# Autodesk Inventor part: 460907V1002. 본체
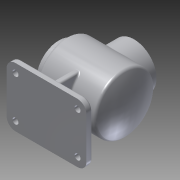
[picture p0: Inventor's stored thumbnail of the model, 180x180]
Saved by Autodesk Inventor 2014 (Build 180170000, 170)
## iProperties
Created: 2016-09
Part Number: 460907V1002. 본체
Material: 알루미늄 6061
Document SubType Name: Modeling
Designer: 702
Density: 2.71 g/cm^3
Appearance: 알루미늄 - 평지
Mass: 1070.91 g
Surface Area: 1277.7 cm^2
Volume: 395.171 cm^3
Author: 702
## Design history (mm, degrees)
sketch "스케치1"
  geometry: L1 (67.5, -50)-(-67.5, -50); L2 (-67.5, -50)-(-67.5, 50); L3 (-67.5, 50)-(67.5, 50); L4 (67.5, 50)-(67.5, -50); 3 further points
  constraints: 8 end point, 2 midpoint, 2 parallel, 1 horizontal, 1 horizontal alignment, 1 perpendicular, 1 vertical alignment
  dimensions: "d0" = 135 distance of L2.end L3.end; "d1" = 100 distance of L1.end L2.end
extrude "돌출1" new body sketch "스케치1" distance "d2" = 10; taper "d3" = 0 deg
node "작업 평면1"
sketch "스케치2"
  geometry: L1 (0, 0)-(0, 10) reference; L2 (0, 10)-(100, 10) reference; L3 (100, 10)-(100, 0) reference; L4 (100, 0)-(0, 0) reference; L5 (50, 0)-(50, 82); C1 r 50 at (50, 82)
  constraints: 2 end point, 1 centre point, 1 coincident, 1 perpendicular
  dimensions: "d4" = 82 distance of L5.start L5.end; "d5" = 100 diameter of C1
extrude "돌출2" join sketch "스케치2" stored distance "d6" = 122; taper "d7" = 0 deg
node "작업 평면2"
sketch "스케치3"
  geometry: L1 (-50, -82)-(-50, -72) reference; L2 (-50, -72)-(50, -72) reference; L3 (50, -72)-(50, -82) reference; L4 (50, -82)-(-50, -82) reference; C1 r 50 at (0, 0) reference; C2 r 38 at (0, 0); 1 further point
  constraints: 1 centre point, 1 coincident
  dimensions: "d9" = 76 diameter of C2
extrude "돌출3" cut sketch "스케치3" stored distance "d10" = 122; taper "d11" = 0 deg
node "작업 평면3"
sketch "스케치4"
  geometry: L1 (61, 132)-(61, 32) reference; L2 (61, 32)-(-49, 32) reference; L3 (-49, 32)-(-49, 44) reference; L4 (-49, 44)-(-61, 44) reference; L5 (-61, 44)-(-61, 120) reference; L6 (-61, 120)-(-49, 120) reference; L7 (-49, 120)-(-49, 132) reference; L8 (-49, 132)-(61, 132) reference; L9 (-67.5, 0)-(-67.5, 10) reference; L10 (-67.5, 10)-(67.5, 10) reference; L11 (67.5, 10)-(67.5, 0) reference; L12 (67.5, 0)-(-67.5, 0) reference; L13 (-61, 82)-(-49, 82); L14 (-49, 120)-(-49, 44); L15 (49.562, 82)-(61, 82); L16 (49.562, 132)-(61, 132); L17 (61, 82)-(61, 132); A1 r 115 centre (-54, 82) between (61, 82) and (49.562, 132); 1 further point
  constraints: 10 end point, 3 collinear, 2 midpoint, 2 point on circle, 1 centre point, 1 tangent
  dimensions: "d14" = 115 radius of A1
revolve "회전1" sketch "스케치4" stored, may be unused: angle "d15" = 90 deg
node "작업 평면4"
fillet "모깎기2" dims "d21" = 3
sketch "스케치6"
  geometry: C1 r 50 at (0, 0) reference; C2 r 41 at (0, 0) reference; C3 r 50 at (0, 0); 1 further point
  constraints: 1 centre point, 1 coincident, 1 concentric
extrude "돌출5" cut sketch "스케치6" distance "d23" = 65; taper "d24" = 0 deg
sketch "스케치7"
  geometry: C1 r 50 at (0, 0) reference; C2 r 38 at (0, 0); 1 further point
  constraints: 1 centre point, 1 coincident
  dimensions: "d26" = 76 diameter of C2
extrude "돌출6" join sketch "스케치7" distance "d27" = 12; taper "d28" = 0 deg
sketch "스케치9"
  geometry: L1 (49.562, 32)-(-49, 32) reference; L2 (-49, 32)-(-49, 44) reference; L3 (-49, 44)-(-61, 44) reference; L4 (-61, 44)-(-61, 120) reference; L5 (-61, 120)-(-49, 120) reference; L6 (-49, 120)-(-49, 132) reference; L7 (-49, 132)-(49.562, 132) reference; L8 (-67.5, 0)-(-67.5, 10) reference; L9 (-67.5, 10)-(67.5, 10) reference; L10 (67.5, 10)-(67.5, 0) reference; L11 (67.5, 0)-(-67.5, 0) reference; L12 (-46, 129)-(47.661, 129); L13 (47.661, 129)-(47.661, 82); L14 (47.661, 82)-(-46, 82); L15 (-46, 82)-(-46, 129); A1 r 115 centre (-54, 82) between (49.562, 32) and (49.562, 132) reference; 1 further point
  constraints: 8 end point, 2 parallel, 1 horizontal, 1 perpendicular
revolve "회전2" sketch "스케치9" stored, may be unused: angle "d32" = 90 deg
sketch "스케치10"
  geometry: C1 r 38 at (0, 0) reference; C2 r 27 at (0, 0); 1 further point
  constraints: 1 centre point, 1 coincident
  dimensions: "d33" = 54 diameter of C2
extrude "돌출8" cut sketch "스케치10" distance "d34" = 25; taper "d35" = 0 deg
node "작업 평면5"
sketch "스케치12"
  geometry: L1 (-49, 44)-(-61, 44) reference; L2 (-49, 32)-(-49, 44) reference; L3 (47.661, 129)-(-46, 129) reference; L4 (-46, 129)-(-46, 109) reference; L5 (-61, 55)-(-46, 55) reference; L6 (-61, 44)-(-61, 55) reference; L7 (49.562, 32)-(-49, 32) reference; L8 (-49, 120)-(-49, 132) reference; L9 (-61, 120)-(-49, 120) reference; L10 (-61, 109)-(-61, 120) reference; L11 (-46, 109)-(-61, 109) reference; L12 (-46, 55)-(-46, 35) reference; L13 (-46, 35)-(47.661, 35) reference; L14 (47.661, 35)-(47.661, 129) reference; L15 (-49, 132)-(49.562, 132) reference; L16 (-67.5, 0)-(-67.5, 10) reference; L17 (-67.5, 10)-(67.5, 10) reference; L18 (67.5, 10)-(67.5, 0) reference; L19 (67.5, 0)-(-67.5, 0) reference; L20 (40.437, 5)-(37.982, 33.071); L21 (37.982, 33.071)-(0, 33.071); L22 (0, 5)-(0, 33.071); L23 (0, 5)-(40.437, 5); L24 (-47.661, 35)-(-47.661, 129); L25 (46, 35)-(-47.661, 35); L26 (-49.562, 32)-(49, 132); L27 (-37.982, 33.071)-(0, 33.071); L28 (-40.437, 5)-(-37.982, 33.071); L29 (0, 5)-(-40.437, 5); L30 (67.5, 10)-(-67.5, 10); L31 (-67.5, 0)-(67.5, 0); A1 r 115 centre (-54, 82) between (49.562, 32) and (49.562, 132) reference; A2 r 115 centre (54, 82) between (-49.562, 132) and (-49.562, 32); 1 further point
  constraints: 24 end point, 13 symmetric about line, 2 perpendicular, 2 point on circle, 1 centre point, 1 parallel, 1 other
extrude "돌출10" join sketch "스케치12" stored distance "d42" = 10; taper "d43" = 0 deg
sketch "스케치13"
  geometry: L1 (55, 32.251)-(55, 10) reference; L2 (55, 10)-(100, 10) reference; L3 (100, 10)-(100, 0) reference; L4 (100, 0)-(0, 0) reference; L5 (0, 0)-(0, 10) reference; L6 (0, 10)-(45, 10) reference; L7 (45, 10)-(45, 32.251) reference; L8 (90, 6.367)-(90, 54.262); L9 (10, 6.367)-(10, 54.262); L10 (10, 6.367)-(90, 6.367); C1 r 47 at (50, 82) reference; A1 r 48.676 centre (50, 82) between (10, 54.262) and (90, 54.262); A2 r 50 centre (50, 82) between (55, 32.251) and (45, 32.251) reference; 2 further points
  constraints: 6 end point, 2 perpendicular, 2 point on circle, 1 centre point, 1 coincident
extrude "돌출11" join sketch "스케치13" stored distance "d45" = 10; taper "d46" = 0 deg
fillet "모깎기4" dims "d47" = 3
fillet "모깎기5" dims "d48" = 3
fillet "모깎기8" dims "d51" = 3
sketch "스케치14" dims "d52" = 65
  geometry: L1 (-50, -72)-(50, -72) reference; L2 (50, -72)-(50, -82) reference; L3 (50, -82)-(-50, -82) reference; L4 (-50, -82)-(-50, -72) reference; L5 (0, 0)-(0, 32.5); C1 r 38 at (0, 0) reference; C2 r 27 at (0, 0) reference; 1 further point
  constraints: 2 end point, 1 coincident, 1 vertical alignment, 2 other
hole "구멍1" sketch "스케치14" at (0, 32.5) diameter "d53" = 3.242; stored, may be unused: countersink angle "d57" = 90 deg, drill point angle "d59" = 118 deg; dims "d54" = 8, "d55" = 4, "d56" = 2, "d58" = 10
fillet "모깎기10" dims "d75" = 15
sketch "스케치16"
  geometry: C1 r 5 at (-52.5, 35); C2 r 5 at (52.5, 35); C3 r 5 at (52.5, -35); C4 r 5 at (-52.5, -35); A1 r 15 centre (-52.5, 35) between (-52.5, 50) and (-67.5, 35) reference; A2 r 15 centre (-52.5, -35) between (-67.5, -35) and (-52.5, -50) reference; A3 r 15 centre (52.5, -35) between (52.5, -50) and (67.5, -35) reference; A4 r 15 centre (52.5, 35) between (67.5, 35) and (52.5, 50) reference; 1 further point
  constraints: 4 centre point, 4 coincident
  dimensions: "d76" = 10 diameter of C1; "d77" = 10 diameter of C2; "d78" = 10 diameter of C3; "d79" = 10 diameter of C4
extrude "돌출12" cut sketch "스케치16" stored distance "d42" = 10; stored distance "d80" = 10; taper "d81" = 0 deg; dims "d101" = 118 deg, "d102" = 40
fillet "모깎기11" dims "d82" = 3
chamfer "모따기1" distance "d83" = 1; stored, may be unused: second distance "d84" = 2, angle "d85" = 45 deg
sketch "스케치17"
  geometry: L1 (-47.661, -47)-(46, -47) reference; L2 (46, -47)-(46, -27) reference; L3 (46, -27)-(60, -27) reference; L4 (60, -27)-(61, -28) reference; L5 (61, -28)-(61, -30.879) reference; L6 (61, -30.879)-(51, -30.879) reference; L7 (51, -30.879)-(50.026, -32.5) reference; L8 (50.026, -32.5)-(51, -34.121) reference; L9 (51, -34.121)-(61, -34.121) reference; L10 (61, -34.121)-(61, -38) reference; L11 (61, -38)-(52, -38) reference; L12 (49, -41)-(49, -50) reference; L13 (49, 50)-(49, 41) reference; L14 (52, 38)-(61, 38) reference; L15 (61, 38)-(61, 34.121) reference; L16 (61, 34.121)-(51, 34.121) reference; L17 (51, 34.121)-(50.026, 32.5) reference; L18 (50.026, 32.5)-(51, 30.879) reference; L19 (51, 30.879)-(61, 30.879) reference; L20 (61, 30.879)-(61, 28) reference; L21 (61, 28)-(60, 27) reference; L22 (60, 27)-(46, 27) reference; L23 (46, 27)-(46, 47) reference; L24 (46, 47)-(-47.661, 47) reference; L25 (-47.661, 47)-(-47.661, -47) reference; L26 (49, 45.5)-(49, -8.146); L27 (49, 0)-(-1, 0); L28 (49, -50)-(-49.562, -50) reference; L29 (-49.562, 50)-(49, 50) reference; C1 r 38 at (-1, 0); A1 r 3 centre (52, -41) between (52, -38) and (49, -41) reference; A2 r 3 centre (52, 41) between (49, 41) and (52, 38) reference; A3 r 115 centre (54, 0) between (-49.562, 50) and (-49.562, -50) reference; 1 further point
  constraints: 4 end point, 1 centre point, 1 coincident, 1 midpoint, 1 parallel, 1 perpendicular, 1 point on line
  dimensions: "d86" = 50 distance of L27.start L27.end; "d87" = 76 diameter of C1
extrude "돌출13" join sketch "스케치17" distance "d88" = 65; taper "d89" = 0 deg
sketch "스케치18"
  geometry: L1 (-46, 35)-(47.661, 35) reference; L2 (47.661, 35)-(47.661, 129) reference; L3 (47.661, 129)-(39, 129) reference; L4 (39, 129)-(39, 82) reference; L5 (39, 82)-(-37, 82) reference; L6 (-37, 82)-(-37, 129) reference; L7 (-37, 129)-(-46, 129) reference; L8 (-46, 129)-(-46, 109) reference; L9 (-46, 109)-(-60, 109) reference; L10 (-60, 109)-(-61, 110) reference; L11 (-61, 110)-(-61, 112.879) reference; L12 (-61, 112.879)-(-51, 112.879) reference; L13 (-51, 112.879)-(-50.026, 114.5) reference; L14 (-50.026, 114.5)-(-51, 116.121) reference; L15 (-51, 116.121)-(-61, 116.121) reference; L16 (-61, 116.121)-(-61, 120) reference; L17 (-61, 120)-(-52, 120) reference; L18 (-49, 123)-(-49, 132) reference; L19 (-49, 132)-(-37, 132) reference; L20 (-37, 132)-(-37, 147) reference; L21 (-37, 147)-(39, 147) reference; L22 (39, 147)-(39, 132) reference; L23 (39, 132)-(49.562, 132) reference; L24 (49.562, 32)-(41.349, 32) reference; L25 (38.361, 28.739)-(40, 10) reference; L26 (40, 10)-(64.5, 10) reference; L27 (67.5, 7)-(67.5, 0) reference; L28 (67.5, 0)-(-67.5, 0) reference; L29 (-67.5, 0)-(-67.5, 7) reference; L30 (-64.5, 10)-(-40, 10) reference; L31 (-40, 10)-(-38.361, 28.739) reference; L32 (-41.349, 32)-(-49, 32) reference; L33 (-49, 32)-(-49, 41) reference; L34 (-52, 44)-(-61, 44) reference; L35 (-61, 44)-(-61, 47.879) reference; L36 (-61, 47.879)-(-51, 47.879) reference; L37 (-51, 47.879)-(-50.026, 49.5) reference; L38 (-50.026, 49.5)-(-51, 51.121) reference; L39 (-51, 51.121)-(-61, 51.121) reference; L40 (-61, 51.121)-(-61, 54) reference; L41 (-61, 54)-(-60, 55) reference; L42 (-60, 55)-(-46, 55) reference; L43 (-46, 55)-(-46, 35) reference; L44 (-46, 129)-(47.661, 129); L45 (47.661, 129)-(47.661, 82); L46 (47.661, 82)-(-46, 82); L47 (-46, 82)-(-46, 129); A1 r 3 centre (-52, 123) between (-52, 120) and (-49, 123) reference; A2 r 3 centre (64.5, 7) between (67.5, 7) and (64.5, 10) reference; A3 r 3 centre (-64.5, 7) between (-64.5, 10) and (-67.5, 7) reference; A4 r 3 centre (-52, 41) between (-49, 41) and (-52, 44) reference; A5 r 115 centre (-54, 82) between (49.562, 32) and (49.562, 132) reference; 1 further point
  constraints: 8 end point, 2 parallel, 1 horizontal, 1 midpoint, 1 perpendicular, 2 other
revolve "회전3" sketch "스케치18" stored, may be unused: angle "d90" = 90 deg
sketch "스케치19"
  geometry: C1 r 38 at (0, 0) reference; C2 r 27 at (0, 0)
  constraints: 1 centre point, 1 coincident
  dimensions: "d91" = 54 diameter of C2
extrude "돌출14" cut sketch "스케치19" distance "d92" = 65; taper "d93" = 0 deg
sketch "스케치20" dims "d94" = 65
  geometry: L1 (0, 0)-(0, 32.5); C1 r 38 at (0, 0) reference; 1 further point
  constraints: 2 end point, 1 coincident, 1 vertical, 1 vertical alignment, 2 other
hole "구멍3" sketch "스케치20" at (0, 32.5) diameter "d95" = 3.242; stored, may be unused: countersink angle "d99" = 90 deg, drill point angle "d101" = 118 deg; dims "d96" = 8, "d97" = 4, "d98" = 2, "d100" = 10
chamfer "모따기2" distance "d105" = 1; stored, may be unused: second distance "d106" = 2, angle "d107" = 45 deg
sketch "스케치21"
  geometry: L1 (-49, 123)-(-49, 132) reference; L2 (-49, 132)-(-37, 132) reference; L3 (-37, 132)-(-37, 147) reference; L4 (-37, 147)-(-33.121, 147) reference; L5 (-33.121, 147)-(-33.121, 137) reference; L6 (-33.121, 137)-(-31.5, 136.026) reference; L7 (-31.5, 136.026)-(-29.879, 137) reference; L8 (-29.879, 137)-(-29.879, 147) reference; L9 (-29.879, 147)-(-27, 147) reference; L10 (-27, 147)-(-26, 146) reference; L11 (-26, 146)-(-26, 129) reference; L12 (-26, 129)-(-46, 129) reference; L13 (-46, 129)-(-46, 109) reference; L14 (-46, 109)-(-60, 109) reference; L15 (-60, 109)-(-61, 110) reference; L16 (-61, 110)-(-61, 112.879) reference; L17 (-61, 112.879)-(-51, 112.879) reference; L18 (-51, 112.879)-(-50.026, 114.5) reference; L19 (-50.026, 114.5)-(-51, 116.121) reference; L20 (-51, 116.121)-(-61, 116.121) reference; L21 (-61, 116.121)-(-61, 120) reference; L22 (-61, 120)-(-52, 120) reference; L23 (-46, 35)-(47.661, 35) reference; L24 (47.661, 35)-(47.661, 129) reference; L25 (47.661, 129)-(28, 129) reference; L26 (28, 129)-(28, 146) reference; L27 (28, 146)-(29, 147) reference; L28 (29, 147)-(31.879, 147) reference; L29 (31.879, 147)-(31.879, 137) reference; L30 (31.879, 137)-(33.5, 136.026) reference; L31 (33.5, 136.026)-(35.121, 137) reference; L32 (35.121, 137)-(35.121, 147) reference; L33 (35.121, 147)-(39, 147) reference; L34 (39, 147)-(39, 132) reference; L35 (39, 132)-(49.562, 132) reference; L36 (49.562, 32)-(41.349, 32) reference; L37 (38.361, 28.739)-(40, 10) reference; L38 (40, 10)-(64.5, 10) reference; L39 (67.5, 7)-(67.5, 0) reference; L40 (67.5, 0)-(-67.5, 0) reference; L41 (-67.5, 0)-(-67.5, 7) reference; L42 (-64.5, 10)-(-40, 10) reference; L43 (-40, 10)-(-38.361, 28.739) reference; L44 (-41.349, 32)-(-49, 32) reference; L45 (-49, 32)-(-49, 41) reference; L46 (-52, 44)-(-61, 44) reference; L47 (-61, 44)-(-61, 47.879) reference; L48 (-61, 47.879)-(-51, 47.879) reference; L49 (-51, 47.879)-(-50.026, 49.5) reference; L50 (-50.026, 49.5)-(-51, 51.121) reference; L51 (-51, 51.121)-(-61, 51.121) reference; L52 (-61, 51.121)-(-61, 54) reference; L53 (-61, 54)-(-60, 55) reference; L54 (-60, 55)-(-46, 55) reference; L55 (-46, 55)-(-46, 35) reference; L56 (37.079, 145.079)-(37.042, 145.079); L57 (29.958, 145.079)-(29.796, 145.079); L58 (29.796, 145.079)-(29.921, 145.204); L59 (-49, 32)-(-49, 52); L60 (-49, 52)-(-58.757, 52); L61 (-58.757, 52)-(-58, 52.757); L62 (-58, 52.757)-(-58, 54.121); L63 (-58, 54.121)-(-49.303, 54.121); L64 (-49.303, 54.121)-(-46.526, 49.5)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; A1 r 3 centre (-52, 123) between (-52, 120) and (-49, 123) reference; A2 r 115 centre (-54, 82) between (49.562, 32) and (49.562, 132) reference; A3 r 3 centre (64.5, 7) between (67.5, 7) and (64.5, 10) reference; A4 r 3 centre (-64.5, 7) between (-64.5, 10) and (-67.5, 7) reference; A5 r 3 centre (-52, 41) between (-49, 41) and (-52, 44) reference; A6 r 6 centre (-52, 41) between (-46, 41) and (-52, 47); A7 r 6 centre (-42.749, 13) between (-42.749, 7) and (-36.772, 12.477); A8 r 112 centre (-54, 82) between (57.998, 82.596) and (47.661, 129); A9 r 3 centre (-52, 123) between (-52, 120) and (-49, 123) reference; A10 r 115 centre (-54, 82) between (49.562, 32) and (49.562, 132) reference; A11 r 3 centre (64.5, 7) between (67.5, 7) and (64.5, 10) reference; A12 r 3 centre (-64.5, 7) between (-64.5, 10) and (-67.5, 7) reference; A13 r 3 centre (-52, 41) between (-49, 41) and (-52, 44) reference
  constraints: 38 end point, 6 point on circle, 3 centre point, 2 parallel, 2 point on line, 1 perpendicular, 26 other
  dimensions: "d110" = 3 radial gap between concentric circles of A2 A8
revolve "회전4" sketch "스케치21" stored, may be unused: angle "d111" = 90 deg
fillet "모깎기13" dims "d112" = 2
fillet "모깎기14" dims "d113" = 5
fillet "모깎기15" dims "d114" = 3
fillet "모깎기17" dims "d116" = 3
fillet "모깎기18" dims "d117" = 3
node "솔리드1"
pattern_circular "원형 패턴1" dims angle "d61" = 360 deg
pattern_circular "원형 패턴3" dims angle "d103" = 360 deg
node "절단 모서리 투영1"
node "절단 모서리 투영2"
node "절단 모서리 투영3"
node "절단 모서리 투영6"
node "절단 모서리 투영7"
node "절단 모서리 투영8"
node "절단 모서리 투영9"
node "절단 모서리 투영10"
node "절단 모서리 투영11"
node "절단 모서리 투영12"
node "절단 모서리 투영13"
other parameters: "d8" = -12, "d12" = 0, "d16" = 82, "d39" = 0
